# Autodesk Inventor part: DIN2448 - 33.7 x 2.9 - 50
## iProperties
Created: 2007-02
Part Number: DIN2448 - 33.7 x 2.9 - 50
Material: Stahl, weich, unlegiert
Description: Rohr
Vendor: Autodesk Inc.
Document SubType Name: Modeling
Standard: DIN2448
Designer: Ing.- und Konstrukti
Standards Organization: DIN
Language: de-DE
Size Designation: 33.7 x 2.9 - 50
Categories: <MemberInstance Version="R10.0.0"><Categories><Category DisplayName="Profilstahle" InternalName="089c4875-fa83-4c05-b084-43b9cc11f5ed" Mnemonic="GRDR"><Category
Stock Number: 33.7 x 2.9
Density: 7.86 g/cm^3
Mass: 132.334 g
Surface Area: 121.725 cm^2
Volume: 16.8364 cm^3
G_L: 50,000 mm
Author: Ing.- und Konstrukti
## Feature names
1. Körper [Extrusion]
